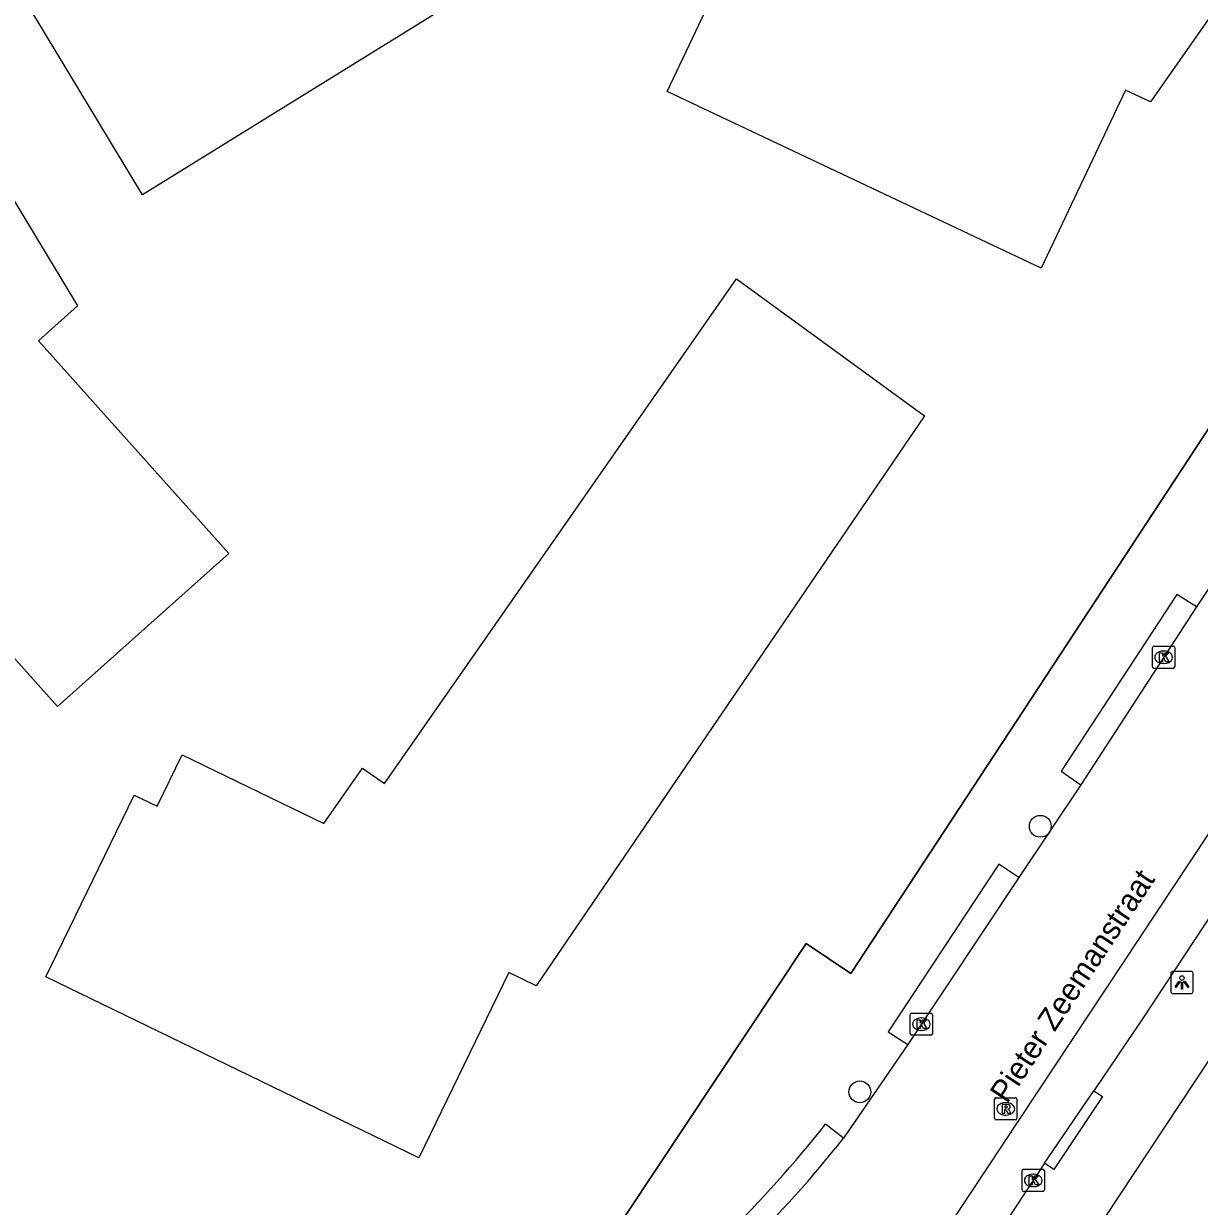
# Model space of a CAD drawing. Extents: x 159280 to 160375, y 384531 to 385872.
# Drawn here: x 159467.8 to 159520.6, y 385202.6 to 385255.7 of the extents above; entities that cross this region are included whole.
import ezdxf

# ---------------------------------------------------------------- set-up
doc = ezdxf.new("R2010")
doc.units = 0
for name, color, linetype in [('IMGEO_Boom', 7, 'Continuous'), ('IMGEO_Groenvoorziening', 7, 'Continuous'), ('IMGEO_Hek', 7, 'Continuous'), ('IMGEO_Kolk', 7, 'Continuous'), ('IMGEO_Lichtpunt', 7, 'Continuous'), ('IMGEO_Openbare_ruimte_label', 7, 'Continuous'), ('IMGEO_Pand_vergunning_verleend', 7, 'Continuous'), ('IMGEO_Rijbaan_lokaal_open', 7, 'Continuous'), ('IMGEO_Rioolput', 7, 'Continuous'), ('IMGEO_Voetpad_open', 7, 'Continuous')]:
    doc.layers.add(name, color=color, linetype=linetype)

msp = doc.modelspace()

# ---------------------------------------------------------------- linework, layer by layer
at = {"layer": 'IMGEO_Boom'}
for centre in [(159513.411, 385219.659), (159505.303, 385207.734)]:
    msp.add_circle(centre, 0.489, dxfattribs=at)
at = {"layer": 'IMGEO_Groenvoorziening'}
msp.add_lwpolyline([(159469.674, 385166.696), (159472.407, 385169.747), (159474.504, 385172.106), (159492.142, 385198.211), (159502.888, 385214.394), (159504.899, 385213.047), (159529.172, 385250), (159546.212, 385275.888)], dxfattribs=at)
at = {"layer": 'IMGEO_Hek'}
msp.add_lwpolyline([(159529.172, 385250), (159504.899, 385213.047), (159502.888, 385214.394), (159492.142, 385198.211), (159474.504, 385172.106), (159472.407, 385169.747), (159469.674, 385166.696)], dxfattribs=at)
at = {"layer": 'IMGEO_Kolk'}
for p, q in [((159518.447, 385226.823), (159518.447, 385227.675)), ((159518.522, 385227.749), (159519.374, 385227.749)), ((159518.935, 385227.529), (159518.96, 385227.529)), ((159519.448, 385227.675), (159519.448, 385226.823)), ((159518.958, 385226.969), (159518.933, 385226.969)), ((159519.374, 385226.749), (159518.522, 385226.749)), ((159507.566, 385210.348), (159507.566, 385211.2)), ((159507.641, 385211.274), (159508.493, 385211.274)), ((159508.054, 385211.054), (159508.079, 385211.054)), ((159508.567, 385211.2), (159508.567, 385210.348)), ((159508.077, 385210.494), (159508.052, 385210.494)), ((159508.493, 385210.274), (159507.641, 385210.274)), ((159512.594, 385203.332), (159512.594, 385204.184)), ((159512.669, 385204.258), (159513.521, 385204.258)), ((159513.082, 385204.038), (159513.107, 385204.038)), ((159513.595, 385204.184), (159513.595, 385203.332)), ((159513.521, 385203.258), (159512.669, 385203.258)), ((159513.105, 385203.478), (159513.08, 385203.478))]:
    msp.add_line(p, q, dxfattribs=at)
for points in [[(159518.447, 385226.823), (159518.447, 385227.675)], [(159518.522, 385227.749), (159519.374, 385227.749)], [(159518.768, 385227.449), (159518.891, 385227.449), (159518.891, 385227.298), (159519.021, 385227.449), (159519.185, 385227.449), (159519.039, 385227.298), (159519.192, 385227.049), (159519.04, 385227.049), (159518.955, 385227.213), (159518.891, 385227.146), (159518.891, 385227.049), (159518.768, 385227.049), (159518.768, 385227.449)], [(159519.448, 385227.675), (159519.448, 385226.823)], [(159519.374, 385226.749), (159518.522, 385226.749)], [(159507.566, 385210.348), (159507.566, 385211.2)], [(159507.641, 385211.274), (159508.493, 385211.274)], [(159507.887, 385210.974), (159508.01, 385210.974), (159508.01, 385210.823), (159508.14, 385210.974), (159508.304, 385210.974), (159508.158, 385210.823), (159508.311, 385210.574), (159508.159, 385210.574), (159508.074, 385210.738), (159508.01, 385210.671), (159508.01, 385210.574), (159507.887, 385210.574), (159507.887, 385210.974)], [(159508.567, 385211.2), (159508.567, 385210.348)], [(159508.493, 385210.274), (159507.641, 385210.274)], [(159512.594, 385203.332), (159512.594, 385204.184)], [(159512.669, 385204.258), (159513.521, 385204.258)], [(159513.595, 385204.184), (159513.595, 385203.332)], [(159512.915, 385203.958), (159513.038, 385203.958), (159513.038, 385203.807), (159513.168, 385203.958), (159513.332, 385203.958), (159513.186, 385203.807), (159513.339, 385203.558), (159513.187, 385203.558), (159513.102, 385203.722), (159513.038, 385203.655), (159513.038, 385203.558), (159512.915, 385203.558), (159512.915, 385203.958)], [(159513.521, 385203.258), (159512.669, 385203.258)]]:
    msp.add_lwpolyline(points, dxfattribs=at)
for centre, start, end in [((159518.524, 385227.673), 91.552, 178.448), ((159518.524, 385227.673), 91.552, 178.448), ((159519.372, 385227.673), 1.552, 88.448), ((159519.372, 385227.673), 1.552, 88.448), ((159518.524, 385226.825), 181.552, 268.448), ((159518.524, 385226.825), 181.552, 268.448), ((159519.372, 385226.825), 271.552, 358.448), ((159519.372, 385226.825), 271.552, 358.448), ((159507.643, 385211.198), 91.552, 178.448), ((159507.643, 385211.198), 91.552, 178.448), ((159508.491, 385211.198), 1.552, 88.448), ((159508.491, 385211.198), 1.552, 88.448), ((159507.643, 385210.35), 181.552, 268.448), ((159507.643, 385210.35), 181.552, 268.448), ((159508.491, 385210.35), 271.552, 358.448), ((159508.491, 385210.35), 271.552, 358.448), ((159512.671, 385204.182), 91.552, 178.448), ((159512.671, 385204.182), 91.552, 178.448), ((159513.519, 385204.182), 1.552, 88.448), ((159513.519, 385204.182), 1.552, 88.448), ((159512.671, 385203.334), 181.552, 268.448), ((159512.671, 385203.334), 181.552, 268.448), ((159513.519, 385203.334), 271.552, 358.448), ((159513.519, 385203.334), 271.552, 358.448)]:
    msp.add_arc(centre, 0.0765, start, end, dxfattribs=at)
for centre, major_axis, ratio, start_param, end_param in [((159518.934, 385227.249), (-0.387, 0.002), 0.722429, 4.712389, 7.853982), ((159518.959, 385227.249), (-0.39, 0.002), 0.717154, 1.570796, 4.712389), ((159508.053, 385210.774), (-0.387, 0.002), 0.722429, 4.712389, 7.853982), ((159508.078, 385210.774), (-0.39, 0.002), 0.717154, 1.570796, 4.712389), ((159513.081, 385203.758), (-0.387, 0.002), 0.722429, 4.712389, 7.853982), ((159513.106, 385203.758), (-0.39, 0.002), 0.717154, 1.570796, 4.712389)]:
    msp.add_ellipse(centre, major_axis=major_axis, ratio=ratio, start_param=start_param, end_param=end_param, dxfattribs=at)
at = {"layer": 'IMGEO_Lichtpunt'}
for p, q in [((159520.174, 385213.144), (159519.366, 385213.144)), ((159520.174, 385213.144), (159519.366, 385213.144)), ((159519.272, 385213.049), (159519.272, 385212.242)), ((159519.272, 385213.049), (159519.272, 385212.242)), ((159520.268, 385212.242), (159520.268, 385213.049)), ((159520.268, 385212.242), (159520.268, 385213.049)), ((159519.366, 385212.148), (159520.174, 385212.148)), ((159519.366, 385212.148), (159520.174, 385212.148))]:
    msp.add_line(p, q, dxfattribs=at)
for points in [[(159519.646, 385212.713), (159519.685, 385212.685), (159519.497, 385212.423), (159519.459, 385212.45), (159519.646, 385212.713)], [(159519.748, 385212.665), (159519.795, 385212.665), (159519.795, 385212.343), (159519.748, 385212.343), (159519.748, 385212.665)], [(159519.858, 385212.685), (159519.896, 385212.712), (159520.083, 385212.45), (159520.044, 385212.422), (159519.858, 385212.685)]]:
    msp.add_lwpolyline(points, dxfattribs=at)
msp.add_circle((159519.771, 385212.847), 0.0994, dxfattribs=at)
for centre, start, end in [((159519.366, 385213.049), 90, 180), ((159519.366, 385213.049), 90, 180), ((159520.174, 385213.049), 0, 90), ((159520.174, 385213.049), 0, 90), ((159519.366, 385212.242), 180, 270), ((159519.366, 385212.242), 180, 270), ((159520.174, 385212.242), 270, 0), ((159520.174, 385212.242), 270, 360)]:
    msp.add_arc(centre, 0.0946, start, end, dxfattribs=at)
at = {"layer": 'IMGEO_Pand_vergunning_verleend'}
for points in [[(159496.66, 385252.651), (159500.362, 385260.489), (159501.361, 385260.018), (159502.546, 385262.527), (159509.273, 385259.35), (159510.595, 385262.149), (159511.859, 385261.266), (159526.151, 385281.718), (159534.746, 385275.587), (159518.36, 385252.185), (159517.233, 385252.717), (159513.456, 385244.718), (159496.66, 385252.651)], [(159467.783, 385256.835), (159488.142, 385269.706), (159486.984, 385271.636), (159490.487, 385273.739), (159491.406, 385272.652), (159498.141, 385278.346), (159505.514, 385269.624), (159498.781, 385263.932), (159495.7, 385262.024), (159494.631, 385263.75), (159492.905, 385262.68), (159493.974, 385260.954), (159473.098, 385248.022), (159467.783, 385256.835)], [(159445.418, 385244.81), (159461.124, 385254.581), (159465.534, 385247.165), (159467.109, 385248.115), (159470.175, 385243.03), (159468.425, 385241.465), (159476.966, 385231.916), (159469.281, 385225.043), (159460.672, 385234.667), (159461.89, 385235.757), (159458.634, 385239.397), (159452.648, 385235.672), (159451.193, 385238.01), (159450.079, 385237.318), (159445.418, 385244.81)], [(159468.752, 385212.898), (159472.711, 385221.059), (159473.742, 385220.559), (159474.865, 385222.874), (159481.236, 385219.784), (159482.972, 385222.272), (159483.963, 385221.581), (159499.764, 385244.237), (159508.203, 385238.094), (159490.769, 385212.5), (159489.54, 385213.096), (159485.502, 385204.772), (159468.752, 385212.898)]]:
    msp.add_lwpolyline(points, dxfattribs=at)
at = {"layer": 'IMGEO_Rijbaan_lokaal_open'}
for points in [[(159522.635, 385232.842), (159520.431, 385229.512)], [(159520.431, 385229.512), (159515.225, 385221.522)], [(159504.103, 385193.86), (159523.226, 385222.717)], [(159515.225, 385221.522), (159512.448, 385217.36)], [(159512.448, 385217.36), (159507.461, 385209.864)], [(159507.461, 385209.864), (159504.576, 385205.661)]]:
    msp.add_lwpolyline(points, dxfattribs=at)
msp.add_arc((159461.671, 385239.588), 54.698, 314.607, 321.6652, dxfattribs=at)
at = {"layer": 'IMGEO_Rioolput'}
for p, q in [((159511.357, 385206.548), (159511.357, 385207.4)), ((159511.432, 385207.474), (159512.284, 385207.474)), ((159511.845, 385207.254), (159511.87, 385207.254)), ((159512.358, 385207.4), (159512.358, 385206.548)), ((159511.868, 385206.694), (159511.843, 385206.694)), ((159512.284, 385206.474), (159511.432, 385206.474))]:
    msp.add_line(p, q, dxfattribs=at)
for points in [[(159511.357, 385206.548), (159511.357, 385207.4)], [(159511.432, 385207.474), (159512.284, 385207.474)], [(159512.358, 385207.4), (159512.358, 385206.548)], [(159511.946, 385207.172), (159511.694, 385207.174), (159511.694, 385206.774)], [(159511.694, 385206.774), (159511.818, 385206.774), (159511.818, 385206.936), (159511.829, 385206.936)], [(159511.872, 385207.093), (159511.818, 385207.093), (159511.818, 385207.012)], [(159511.818, 385207.012), (159511.87, 385207.012)], [(159511.876, 385206.907), (159511.947, 385206.774), (159512.087, 385206.774), (159512.022, 385206.9)], [(159512.284, 385206.474), (159511.432, 385206.474)]]:
    msp.add_lwpolyline(points, dxfattribs=at)
for centre, radius, start, end in [((159511.434, 385207.398), 0.0765, 91.552, 178.448), ((159511.434, 385207.398), 0.0765, 91.552, 178.448), ((159512.282, 385207.398), 0.0765, 1.552, 88.448), ((159512.282, 385207.398), 0.0765, 1.552, 88.448), ((159511.828, 385206.883), 0.0533, 26.0293, 88.6989), ((159511.854, 385207.201), 0.19, 274.7715, 282.9687), ((159511.878, 385206.997), 0.0964, 77.0061, 93.1865), ((159511.892, 385207.054), 0.0378, 276.6634, 79.6772), ((159511.945, 385207.062), 0.109, 350.3612, 89.416), ((159511.943, 385207.062), 0.112, 277.5842, 350.9817), ((159511.927, 385206.847), 0.108, 29.5134, 73.7905), ((159511.434, 385206.55), 0.0765, 181.552, 268.448), ((159511.434, 385206.55), 0.0765, 181.552, 268.448), ((159512.282, 385206.55), 0.0765, 271.552, 358.448), ((159512.282, 385206.55), 0.0765, 271.552, 358.448)]:
    msp.add_arc(centre, radius, start, end, dxfattribs=at)
for centre, major_axis, ratio, start_param, end_param in [((159511.844, 385206.974), (-0.387, 0.002), 0.722429, 4.712389, 7.853982), ((159511.869, 385206.974), (-0.39, 0.002), 0.717154, 1.570796, 4.712389)]:
    msp.add_ellipse(centre, major_axis=major_axis, ratio=ratio, start_param=start_param, end_param=end_param, dxfattribs=at)
at = {"layer": 'IMGEO_Voetpad_open'}
for points in [[(159520.431, 385229.512), (159519.542, 385230.066), (159514.344, 385222.135), (159515.225, 385221.522)], [(159530.535, 385223.584), (159500, 385177.475), (159492.38, 385165.468)], [(159523.226, 385222.717), (159523.169, 385222.622), (159523.093, 385222.461), (159523.032, 385222.294), (159522.986, 385222.122), (159522.956, 385221.947), (159522.941, 385221.77), (159522.942, 385221.592), (159522.959, 385221.415), (159522.989, 385221.253), (159523.326, 385219.705), (159523.331, 385219.675), (159523.342, 385219.563), (159523.344, 385219.45), (159523.335, 385219.337), (159523.316, 385219.225), (159523.288, 385219.115), (159523.25, 385219.009), (159523.202, 385218.906), (159523.145, 385218.808), (159523.08, 385218.715), (159518, 385211.012), (159515.809, 385207.785)], [(159512.448, 385217.36), (159511.549, 385217.953), (159506.582, 385210.436), (159507.461, 385209.864)], [(159515.809, 385207.785), (159516.199, 385207.525), (159514.017, 385204.25), (159513.601, 385204.527)], [(159513.601, 385204.527), (159513.763, 385204.772), (159515.809, 385207.785)], [(159504.576, 385205.661), (159503.765, 385206.282)], [(159513.601, 385204.527), (159505.818, 385192.716)]]:
    msp.add_lwpolyline(points, dxfattribs=at)
msp.add_arc((159460.86, 385240.209), 54.698, 314.607, 321.6652, dxfattribs=at)

# ---------------------------------------------------------------- texts
at = {"layer": 'IMGEO_Openbare_ruimte_label'}
msp.add_text('Pieter Zeemanstraat', height=1, rotation=56.58, dxfattribs=at).set_placement((159511.922, 385207.171))

doc.saveas('drawing.dxf')
